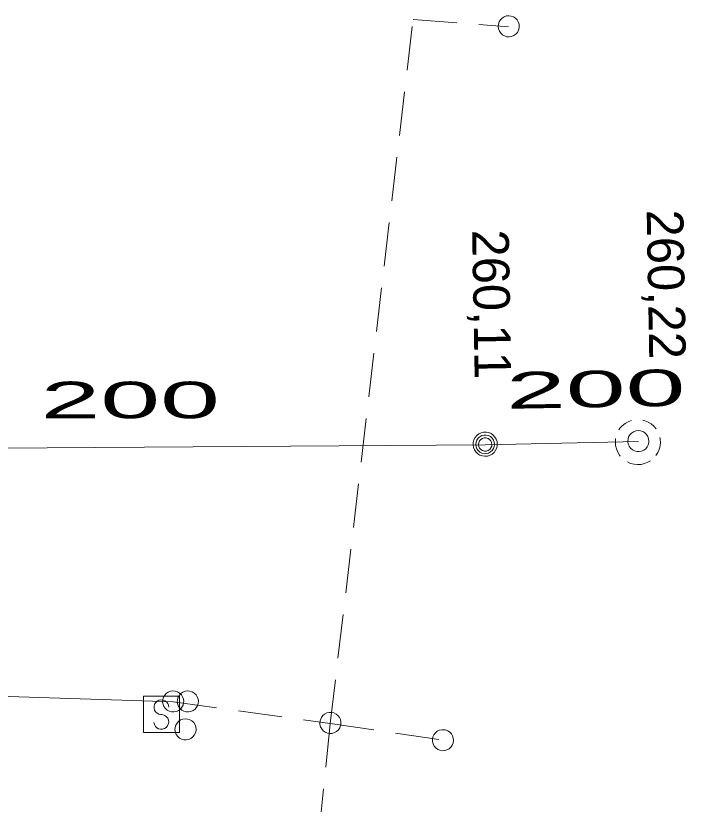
# Model space of a CAD drawing. Extents: x -732096 to -731933, y -1048703 to -1047964.
# Drawn here: x -732026 to -732011.33, y -1048029.6 to -1048012.34 of the extents above; entities that cross this region are included whole.
import ezdxf

# ---------------------------------------------------------------- set-up
doc = ezdxf.new("R2010")
doc.units = 0
doc.header["$LTSCALE"] = 0.32
doc.linetypes.add('MEDIUM_DASHED', pattern=[4.5, 3, -1.5])
doc.layers.add('1', color=7, linetype='Continuous')
for name, color, linetype, lineweight in [('18', 7, 'Continuous', 13), ('49', 7, 'Continuous', 13), ('8', 7, 'Continuous', 13)]:
    doc.layers.add(name, color=color, linetype=linetype, lineweight=lineweight)

msp = doc.modelspace()

# ---------------------------------------------------------------- linework, layer by layer
at = {"layer": '18'}
for points in [[(-732012.532, -1048021.197), (-732012.603, -1048021.225), (-732012.669, -1048021.264), (-732012.73, -1048021.312), (-732012.781, -1048021.369), (-732012.804, -1048021.403)], [(-732011.99, -1048021.38), (-732012.041, -1048021.322), (-732012.098, -1048021.272), (-732012.164, -1048021.231), (-732012.235, -1048021.202), (-732012.284, -1048021.188)], [(-732012.877, -1048021.589), (-732012.882, -1048021.666), (-732012.877, -1048021.743), (-732012.86, -1048021.818), (-732012.831, -1048021.889), (-732012.791, -1048021.955), (-732012.776, -1048021.977)], [(-732011.995, -1048021.966), (-732011.955, -1048021.901), (-732011.924, -1048021.831), (-732011.904, -1048021.756), (-732011.897, -1048021.68), (-732011.902, -1048021.603), (-732011.907, -1048021.568)], [(-732012.619, -1048022.106), (-732012.549, -1048022.137), (-732012.473, -1048022.156), (-732012.397, -1048022.163), (-732012.321, -1048022.158), (-732012.245, -1048022.141), (-732012.174, -1048022.113), (-732012.114, -1048022.078)]]:
    msp.add_lwpolyline(points, dxfattribs=at)
for points in [[(-732012.147, -1048021.649), (-732012.154, -1048021.597), (-732012.171, -1048021.547), (-732012.2, -1048021.503), (-732012.238, -1048021.466), (-732012.282, -1048021.439), (-732012.333, -1048021.423), (-732012.385, -1048021.418), (-732012.436, -1048021.425), (-732012.485, -1048021.444), (-732012.529, -1048021.474), (-732012.565, -1048021.513), (-732012.591, -1048021.558), (-732012.605, -1048021.609), (-732012.608, -1048021.661), (-732012.6, -1048021.713), (-732012.58, -1048021.761), (-732012.549, -1048021.804), (-732012.51, -1048021.839), (-732012.463, -1048021.863), (-732012.413, -1048021.877), (-732012.36, -1048021.879), (-732012.309, -1048021.869), (-732012.261, -1048021.847), (-732012.218, -1048021.815), (-732012.186, -1048021.775), (-732012.162, -1048021.728), (-732012.149, -1048021.677)], [(-732015.466, -1048021.717), (-732015.472, -1048021.661), (-732015.489, -1048021.608), (-732015.517, -1048021.559), (-732015.556, -1048021.518), (-732015.602, -1048021.486), (-732015.654, -1048021.464), (-732015.709, -1048021.453), (-732015.765, -1048021.455), (-732015.82, -1048021.468), (-732015.87, -1048021.493), (-732015.915, -1048021.528), (-732015.951, -1048021.571), (-732015.976, -1048021.621), (-732015.991, -1048021.676), (-732015.994, -1048021.732), (-732015.985, -1048021.787), (-732015.964, -1048021.84), (-732015.933, -1048021.886), (-732015.892, -1048021.925), (-732015.845, -1048021.955), (-732015.792, -1048021.974), (-732015.736, -1048021.981), (-732015.679, -1048021.977), (-732015.625, -1048021.96), (-732015.576, -1048021.933), (-732015.535, -1048021.895), (-732015.502, -1048021.85), (-732015.478, -1048021.799), (-732015.467, -1048021.744)], [(-732015.525, -1048021.72), (-732015.531, -1048021.671), (-732015.549, -1048021.625), (-732015.576, -1048021.584), (-732015.614, -1048021.551), (-732015.657, -1048021.529), (-732015.706, -1048021.517), (-732015.755, -1048021.517), (-732015.803, -1048021.529), (-732015.847, -1048021.552), (-732015.884, -1048021.585), (-732015.912, -1048021.626), (-732015.929, -1048021.673), (-732015.934, -1048021.722), (-732015.928, -1048021.771), (-732015.91, -1048021.817), (-732015.882, -1048021.857), (-732015.845, -1048021.89), (-732015.801, -1048021.912), (-732015.752, -1048021.924), (-732015.703, -1048021.923), (-732015.655, -1048021.911), (-732015.612, -1048021.887), (-732015.575, -1048021.854), (-732015.547, -1048021.813), (-732015.531, -1048021.766)], [(-732015.584, -1048021.724), (-732015.59, -1048021.682), (-732015.607, -1048021.644), (-732015.635, -1048021.613), (-732015.669, -1048021.59), (-732015.71, -1048021.579), (-732015.752, -1048021.579), (-732015.792, -1048021.591), (-732015.826, -1048021.614), (-732015.853, -1048021.646), (-732015.87, -1048021.684), (-732015.875, -1048021.725), (-732015.87, -1048021.767), (-732015.852, -1048021.804), (-732015.824, -1048021.836), (-732015.788, -1048021.858), (-732015.748, -1048021.869), (-732015.706, -1048021.868), (-732015.666, -1048021.855), (-732015.632, -1048021.832), (-732015.605, -1048021.799), (-732015.589, -1048021.761)]]:
    msp.add_lwpolyline(points, close=True, dxfattribs=at)
at = {"layer": '49'}
for p, q in [((-732015.73, -1048021.73), (-732032.882, -1048021.854)), ((-732015.73, -1048021.73), (-732032.882, -1048021.854)), ((-732012.379, -1048021.66), (-732015.73, -1048021.73)), ((-732012.379, -1048021.66), (-732015.73, -1048021.73))]:
    msp.add_line(p, q, dxfattribs=at)
at = {"layer": '8'}
msp.add_line((-732038.559, -1048026.84), (-732022.559, -1048027.36), dxfattribs=at)
at = {"layer": '8', "linetype": 'MEDIUM_DASHED'}
for p, q in [((-732022.559, -1048027.36), (-732019.12, -1048027.83)), ((-732019.12, -1048027.83), (-732016.646, -1048028.2))]:
    msp.add_line(p, q, dxfattribs=at)
for points in [[(-732019.12, -1048027.83), (-732017.309, -1048012.42), (-732015.217, -1048012.58)], [(-732019.12, -1048027.83), (-732021.05, -1048046.46), (-732018.874, -1048046.779)]]:
    msp.add_lwpolyline(points, dxfattribs=at)
at = {"layer": '8'}
for points in [[(-732014.985, -1048012.576), (-732014.99, -1048012.523), (-732015.006, -1048012.473), (-732015.033, -1048012.428), (-732015.069, -1048012.39), (-732015.113, -1048012.361), (-732015.163, -1048012.344), (-732015.215, -1048012.337), (-732015.267, -1048012.342), (-732015.316, -1048012.36), (-732015.361, -1048012.388), (-732015.398, -1048012.426), (-732015.425, -1048012.47), (-732015.442, -1048012.521), (-732015.446, -1048012.573), (-732015.44, -1048012.625), (-732015.421, -1048012.673), (-732015.392, -1048012.717), (-732015.353, -1048012.754), (-732015.308, -1048012.779), (-732015.258, -1048012.795), (-732015.206, -1048012.798), (-732015.153, -1048012.79), (-732015.105, -1048012.77), (-732015.062, -1048012.739), (-732015.027, -1048012.7), (-732015.002, -1048012.654), (-732014.988, -1048012.603)], [(-732022.328, -1048027.349), (-732022.334, -1048027.297), (-732022.352, -1048027.247), (-732022.38, -1048027.203), (-732022.418, -1048027.166), (-732022.463, -1048027.139), (-732022.513, -1048027.123), (-732022.565, -1048027.118), (-732022.617, -1048027.125), (-732022.666, -1048027.144), (-732022.71, -1048027.174), (-732022.745, -1048027.213), (-732022.771, -1048027.258), (-732022.786, -1048027.309), (-732022.789, -1048027.361), (-732022.781, -1048027.413), (-732022.76, -1048027.461), (-732022.73, -1048027.504), (-732022.69, -1048027.539), (-732022.644, -1048027.563), (-732022.593, -1048027.577), (-732022.541, -1048027.579), (-732022.489, -1048027.569), (-732022.441, -1048027.547), (-732022.399, -1048027.515), (-732022.366, -1048027.475), (-732022.342, -1048027.428), (-732022.33, -1048027.377)], [(-732022.007, -1048027.349), (-732022.014, -1048027.297), (-732022.031, -1048027.247), (-732022.059, -1048027.203), (-732022.098, -1048027.166), (-732022.142, -1048027.139), (-732022.193, -1048027.123), (-732022.245, -1048027.118), (-732022.296, -1048027.125), (-732022.345, -1048027.144), (-732022.389, -1048027.174), (-732022.424, -1048027.213), (-732022.451, -1048027.258), (-732022.465, -1048027.309), (-732022.468, -1048027.361), (-732022.46, -1048027.413), (-732022.44, -1048027.461), (-732022.409, -1048027.504), (-732022.37, -1048027.539), (-732022.323, -1048027.563), (-732022.272, -1048027.577), (-732022.22, -1048027.579), (-732022.169, -1048027.569), (-732022.12, -1048027.547), (-732022.078, -1048027.515), (-732022.046, -1048027.475), (-732022.022, -1048027.428), (-732022.009, -1048027.377)], [(-732023.206, -1048027.23), (-732022.417, -1048027.23), (-732022.417, -1048028.03), (-732023.206, -1048028.03)], [(-732018.889, -1048027.85), (-732018.888, -1048027.798), (-732018.899, -1048027.746), (-732018.921, -1048027.699), (-732018.954, -1048027.657), (-732018.995, -1048027.624), (-732019.042, -1048027.601), (-732019.093, -1048027.589), (-732019.145, -1048027.589), (-732019.196, -1048027.601), (-732019.244, -1048027.625), (-732019.284, -1048027.659), (-732019.316, -1048027.7), (-732019.338, -1048027.749), (-732019.348, -1048027.8), (-732019.347, -1048027.852), (-732019.332, -1048027.903), (-732019.308, -1048027.95), (-732019.274, -1048027.99), (-732019.231, -1048028.02), (-732019.183, -1048028.04), (-732019.131, -1048028.049), (-732019.079, -1048028.047), (-732019.028, -1048028.031), (-732018.982, -1048028.005), (-732018.944, -1048027.97), (-732018.914, -1048027.927), (-732018.895, -1048027.878)], [(-732022.058, -1048027.959), (-732022.064, -1048027.907), (-732022.081, -1048027.857), (-732022.11, -1048027.813), (-732022.148, -1048027.776), (-732022.193, -1048027.749), (-732022.243, -1048027.733), (-732022.295, -1048027.728), (-732022.347, -1048027.735), (-732022.396, -1048027.754), (-732022.44, -1048027.784), (-732022.475, -1048027.823), (-732022.501, -1048027.868), (-732022.516, -1048027.919), (-732022.519, -1048027.971), (-732022.511, -1048028.023), (-732022.49, -1048028.071), (-732022.46, -1048028.114), (-732022.42, -1048028.149), (-732022.374, -1048028.173), (-732022.323, -1048028.187), (-732022.271, -1048028.189), (-732022.219, -1048028.179), (-732022.171, -1048028.157), (-732022.129, -1048028.125), (-732022.096, -1048028.085), (-732022.072, -1048028.038), (-732022.059, -1048027.987)], [(-732016.628, -1048027.968), (-732016.68, -1048027.968), (-732016.732, -1048027.98), (-732016.779, -1048028.002), (-732016.82, -1048028.036), (-732016.852, -1048028.077), (-732016.874, -1048028.125), (-732016.885, -1048028.176), (-732016.884, -1048028.229), (-732016.871, -1048028.28), (-732016.846, -1048028.327), (-732016.812, -1048028.366), (-732016.77, -1048028.397), (-732016.721, -1048028.418), (-732016.67, -1048028.427), (-732016.617, -1048028.425), (-732016.567, -1048028.41), (-732016.521, -1048028.385), (-732016.482, -1048028.35), (-732016.452, -1048028.307), (-732016.432, -1048028.258), (-732016.424, -1048028.206), (-732016.428, -1048028.153), (-732016.445, -1048028.103), (-732016.471, -1048028.058), (-732016.507, -1048028.02), (-732016.551, -1048027.991), (-732016.6, -1048027.973)]]:
    msp.add_lwpolyline(points, close=True, dxfattribs=at)
for points in [[(-732022.657, -1048027.476), (-732022.663, -1048027.433), (-732022.679, -1048027.392), (-732022.706, -1048027.358), (-732022.743, -1048027.332), (-732022.784, -1048027.317), (-732022.827, -1048027.314), (-732022.87, -1048027.322), (-732022.909, -1048027.342), (-732022.942, -1048027.371), (-732022.965, -1048027.409), (-732022.977, -1048027.451), (-732022.978, -1048027.494), (-732022.966, -1048027.537), (-732022.944, -1048027.574), (-732022.912, -1048027.605), (-732022.874, -1048027.625), (-732022.831, -1048027.634), (-732022.804, -1048027.634)], [(-732022.98, -1048027.813), (-732022.97, -1048027.856), (-732022.948, -1048027.895), (-732022.917, -1048027.926), (-732022.879, -1048027.947), (-732022.836, -1048027.958), (-732022.792, -1048027.956), (-732022.75, -1048027.943), (-732022.713, -1048027.919), (-732022.684, -1048027.886), (-732022.665, -1048027.846), (-732022.657, -1048027.803), (-732022.661, -1048027.759), (-732022.677, -1048027.718), (-732022.703, -1048027.683), (-732022.738, -1048027.656), (-732022.779, -1048027.639), (-732022.804, -1048027.634)]]:
    msp.add_lwpolyline(points, dxfattribs=at)

# ---------------------------------------------------------------- texts
at = {"layer": '1'}
for s, p in [('260,22', (-732012.197, -1048016.588)), ('260,11', (-732016.017, -1048017.024))]:
    msp.add_text(s, height=0.8, rotation=271, dxfattribs=at).set_placement(p)
at = {"layer": '1', "width": 2.2}
msp.add_text('200 ', height=0.8, rotation=1, dxfattribs=at).set_placement((-732015.269, -1048020.942))
msp.add_text('200 ', height=0.8, dxfattribs=at).set_placement((-732025.463, -1048021.148))

doc.saveas('drawing.dxf')
